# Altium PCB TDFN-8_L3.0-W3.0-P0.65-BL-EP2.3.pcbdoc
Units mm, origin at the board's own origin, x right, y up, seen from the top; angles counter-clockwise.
Board outline 15.85 x 16.43 mm, 2 copper layers (Top Layer, Bottom Layer), stack 0 mm thick; 1 components, 0 nets, 9 pads, 0 vias.
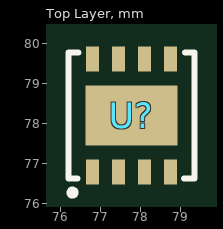
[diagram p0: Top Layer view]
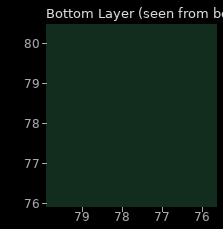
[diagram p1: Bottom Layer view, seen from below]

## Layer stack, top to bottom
Top Layer: signal copper (thickness not stored)
Bottom Layer: signal copper (thickness not stored)

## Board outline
85.702,69.85 69.85,69.85 69.85,86.28 85.702,86.28

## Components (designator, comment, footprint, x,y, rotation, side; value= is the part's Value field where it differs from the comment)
U? "" TDFN-8_L3.0-W3.0-P0.65-BL-EP2.3 77.776,78.205 r0 top

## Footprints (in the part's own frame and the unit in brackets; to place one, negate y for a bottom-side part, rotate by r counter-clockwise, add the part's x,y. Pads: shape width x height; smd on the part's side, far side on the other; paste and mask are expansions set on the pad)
TDFN-8_L3.0-W3.0-P0.65-BL-EP2.3 [mm]
  rect 0.32x0.625 smd: 1(-0.975,-1.412) 2(-0.325,-1.412) 3(0.325,-1.412) 4(0.975,-1.412) 5(0.975,1.412) 6(0.325,1.412) 7(-0.325,1.412) 8(-0.975,1.412)
  rect 2.3x1.5 smd: 9(0,0)
  silkscreen extent -1.58,-2.01 1.58,1.58

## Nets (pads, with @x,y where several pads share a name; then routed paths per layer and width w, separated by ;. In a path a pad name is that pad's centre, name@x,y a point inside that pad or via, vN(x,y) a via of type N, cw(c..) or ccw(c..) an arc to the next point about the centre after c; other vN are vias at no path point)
pads on no net: U?.1 U?.2 U?.3 U?.4 U?.5 U?.6 U?.7 U?.8 U?.9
